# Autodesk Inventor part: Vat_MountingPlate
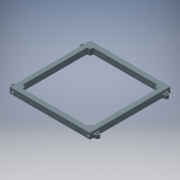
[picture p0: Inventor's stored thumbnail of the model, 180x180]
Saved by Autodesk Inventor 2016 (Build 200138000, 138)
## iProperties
Created: 2015-11
Part Number: Vat_MountingPlate
Material: Generic
Document SubType Name: Modeling
Designer: John
Density: 1 g/cm^3
Appearance: Default
Author: John
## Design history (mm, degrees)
feature "Base1"
sketch "Sketch1"
  geometry: L1 (8, 17.2)-(8, 16.2) reference; L2 (3.5, 20.7)-(4.5, 20.7) reference; L3 (0, 0)-(0, 24.2) reference; L4 (187.3, 0)-(0, 0) reference; L5 (187.3, 0)-(187.3, 24.2) reference; L6 (183.8, 20.7)-(182.8, 20.7) reference; L7 (179.3, 17.2)-(179.3, 16.2) reference; L8 (175.8, 12.7)-(11.5, 12.7) reference; L9 (3.5, 192)-(4.5, 192) reference; L10 (8, 195.5)-(8, 196.5) reference; L11 (11.5, 200)-(175.8, 200) reference; L12 (179.3, 195.5)-(179.3, 196.5) reference; L13 (183.8, 192)-(182.8, 192) reference; L14 (187.3, 188.5)-(187.3, 212.7) reference; L15 (187.3, 212.7)-(0, 212.7) reference; L16 (0, 188.5)-(0, 212.7) reference; C1 r 1.75 at (183.3, 16.7) reference; C2 r 1.75 at (4, 16.7) reference; C3 r 1.75 at (4, 196) reference; C4 r 1.75 at (183.3, 196) reference; A1 r 3.5 centre (4.5, 17.2) between (8, 17.2) and (4.5, 20.7) reference; A2 r 3.5 centre (3.5, 24.2) between (0, 24.2) and (3.5, 20.7) reference; A3 r 3.5 centre (183.8, 24.2) between (183.8, 20.7) and (187.3, 24.2) reference; A4 r 3.5 centre (182.8, 17.2) between (182.8, 20.7) and (179.3, 17.2) reference; A5 r 3.5 centre (175.8, 16.2) between (175.8, 12.7) and (179.3, 16.2) reference; A6 r 3.5 centre (11.5, 16.2) between (8, 16.2) and (11.5, 12.7) reference; A7 r 3.5 centre (4.5, 195.5) between (4.5, 192) and (8, 195.5) reference; A8 r 3.5 centre (11.5, 196.5) between (11.5, 200) and (8, 196.5) reference; A9 r 3.5 centre (175.8, 196.5) between (179.3, 196.5) and (175.8, 200) reference; A10 r 3.5 centre (182.8, 195.5) between (179.3, 195.5) and (182.8, 192) reference; A11 r 3.5 centre (183.8, 188.5) between (187.3, 188.5) and (183.8, 192) reference; A12 r 3.5 centre (3.5, 188.5) between (3.5, 192) and (0, 188.5) reference; 1 further point
extrude "Extrusion1" join sketch "Sketch1" stored distance "d0" = 10; taper "d1" = 0 deg
sketch "Sketch2"
  geometry: L1 (212.7, 19.35)-(212.7, 0) reference; L2 (210.7, 21.35)-(202, 21.35) reference; L3 (200, 19.35)-(200, 21.35) reference; L4 (12.7, 21.35)-(200, 21.35) reference; L5 (12.7, 19.35)-(12.7, 21.35) reference; L6 (2, 21.35)-(10.7, 21.35) reference; L7 (0, 0)-(0, 19.35) reference; L8 (212.7, 0)-(0, 0) reference; L9 (202, 21.35)-(200, 21.35); L10 (10.7, 21.35)-(12.7, 21.35); C1 r 4.25 at (6.35, 13.85) reference; C2 r 4.25 at (206.35, 13.85) reference; A1 r 2 centre (210.7, 19.35) between (212.7, 19.35) and (210.7, 21.35) reference; A2 r 2 centre (202, 19.35) between (202, 21.35) and (200, 19.35) reference; A3 r 2 centre (10.7, 19.35) between (12.7, 19.35) and (10.7, 21.35) reference; A4 r 2 centre (2, 19.35) between (2, 21.35) and (0, 19.35) reference; 1 further point
  constraints: 4 end point, 1 collinear, 1 horizontal, 1 tangent
extrude "Extrusion2" join sketch "Sketch2" stored distance "d2" = 10; taper "d3" = 0 deg
sketch "Sketch3"
  geometry: L1 (212.7, -25)-(212.7, -187.7) reference; L2 (212.7, 0)-(212.7, -5) reference; L3 (0, 0)-(212.7, 0) reference; L4 (0, 0)-(0, -5) reference; L5 (0, -25)-(0, -187.7) reference; L6 (0, -207.7)-(0, -212.7) reference; L7 (0, -212.7)-(212.7, -212.7) reference; L8 (212.7, -207.7)-(212.7, -212.7) reference; L9 (17.2, -20.7)-(16.2, -20.7) reference; L10 (20.7, -16.2)-(20.7, -17.2) reference; L11 (188.5, -12.7)-(24.2, -12.7) reference; L12 (192, -16.2)-(192, -17.2) reference; L13 (195.5, -20.7)-(196.5, -20.7) reference; L14 (200, -188.5)-(200, -24.2) reference; L15 (195.5, -192)-(196.5, -192) reference; L16 (192, -196.5)-(192, -195.5) reference; L17 (24.2, -200)-(188.5, -200) reference; L18 (20.7, -196.5)-(20.7, -195.5) reference; L19 (17.2, -192)-(16.2, -192) reference; L20 (12.7, -24.2)-(12.7, -188.5) reference; C1 r 1.75 at (196, -16.7) reference; C2 r 1.75 at (16.7, -16.7) reference; C3 r 1.75 at (16.7, -196) reference; C4 r 1.75 at (196, -196) reference; C5 r 1.75 at (217.7, -197.7) reference; C6 r 1.75 at (-5, -197.7) reference; C7 r 1.75 at (-5, -15) reference; C8 r 1.75 at (217.7, -15) reference; A1 r 5 centre (217.7, -25) between (217.7, -20) and (212.7, -25) reference; A2 r 5 centre (217.7, -15) between (217.7, -20) and (217.7, -10) reference; A3 r 5 centre (217.7, -5) between (212.7, -5) and (217.7, -10) reference; A4 r 5 centre (-5, -5) between (-5, -10) and (0, -5) reference; A5 r 5 centre (-5, -15) between (-5, -10) and (-5, -20) reference; A6 r 5 centre (-5, -25) between (0, -25) and (-5, -20) reference; A7 r 5 centre (-5, -187.7) between (-5, -192.7) and (0, -187.7) reference; A8 r 5 centre (-5, -197.7) between (-5, -192.7) and (-5, -202.7) reference; A9 r 5 centre (-5, -207.7) between (0, -207.7) and (-5, -202.7) reference; A10 r 5 centre (217.7, -207.7) between (217.7, -202.7) and (212.7, -207.7) reference; A11 r 5 centre (217.7, -197.7) between (217.7, -202.7) and (217.7, -192.7) reference; A12 r 5 centre (217.7, -187.7) between (212.7, -187.7) and (217.7, -192.7) reference; A13 r 3.5 centre (17.2, -17.2) between (17.2, -20.7) and (20.7, -17.2) reference; A14 r 3.5 centre (24.2, -16.2) between (24.2, -12.7) and (20.7, -16.2) reference; A15 r 3.5 centre (188.5, -16.2) between (192, -16.2) and (188.5, -12.7) reference; A16 r 3.5 centre (195.5, -17.2) between (192, -17.2) and (195.5, -20.7) reference; A17 r 3.5 centre (196.5, -24.2) between (200, -24.2) and (196.5, -20.7) reference; A18 r 3.5 centre (196.5, -188.5) between (196.5, -192) and (200, -188.5) reference; A19 r 3.5 centre (195.5, -195.5) between (195.5, -192) and (192, -195.5) reference; A20 r 3.5 centre (188.5, -196.5) between (188.5, -200) and (192, -196.5) reference; A21 r 3.5 centre (24.2, -196.5) between (20.7, -196.5) and (24.2, -200) reference; A22 r 3.5 centre (17.2, -195.5) between (20.7, -195.5) and (17.2, -192) reference; A23 r 3.5 centre (16.2, -188.5) between (12.7, -188.5) and (16.2, -192) reference; A24 r 3.5 centre (16.2, -24.2) between (16.2, -20.7) and (12.7, -24.2) reference; 1 further point
extrude "Extrusion3" cut sketch "Sketch3" distance "d4" = 6; taper "d5" = 0 deg
sketch "Sketch4"
  geometry: L1 (17.2, -20.7)-(16.2, -20.7) reference; L2 (20.7, -16.2)-(20.7, -17.2) reference; L3 (188.5, -12.7)-(24.2, -12.7) reference; L4 (192, -17.2)-(192, -16.2) reference; L5 (196.5, -20.7)-(195.5, -20.7) reference; L6 (200, -188.5)-(200, -24.2) reference; L7 (195.5, -192)-(196.5, -192) reference; L8 (192, -196.5)-(192, -195.5) reference; L9 (24.2, -200)-(188.5, -200) reference; L10 (20.7, -195.5)-(20.7, -196.5) reference; L11 (16.2, -192)-(17.2, -192) reference; L12 (12.7, -24.2)-(12.7, -188.5) reference; L13 (212.7, -25)-(212.7, -187.7) reference; L14 (212.7, 0)-(212.7, -5) reference; L15 (0, 0)-(212.7, 0) reference; L16 (0, -5)-(0, 0) reference; L17 (0, -187.7)-(0, -25) reference; L18 (0, -212.7)-(0, -207.7) reference; L19 (212.7, -212.7)-(0, -212.7) reference; L20 (212.7, -207.7)-(212.7, -212.7) reference; C1 r 1.75 at (217.7, -15) reference; C2 r 1.75 at (-5, -15) reference; C3 r 1.75 at (-5, -197.7) reference; C4 r 1.75 at (217.7, -197.7) reference; C5 r 1.75 at (196, -196) reference; C6 r 1.75 at (16.7, -196) reference; C7 r 1.75 at (16.7, -16.7) reference; C8 r 1.75 at (196, -16.7) reference; A1 r 3.5 centre (16.2, -24.2) between (16.2, -20.7) and (12.7, -24.2) reference; A2 r 3.5 centre (17.2, -17.2) between (17.2, -20.7) and (20.7, -17.2) reference; A3 r 3.5 centre (24.2, -16.2) between (24.2, -12.7) and (20.7, -16.2) reference; A4 r 3.5 centre (188.5, -16.2) between (192, -16.2) and (188.5, -12.7) reference; A5 r 3.5 centre (195.5, -17.2) between (192, -17.2) and (195.5, -20.7) reference; A6 r 3.5 centre (196.5, -24.2) between (200, -24.2) and (196.5, -20.7) reference; A7 r 3.5 centre (196.5, -188.5) between (196.5, -192) and (200, -188.5) reference; A8 r 3.5 centre (195.5, -195.5) between (195.5, -192) and (192, -195.5) reference; A9 r 3.5 centre (188.5, -196.5) between (188.5, -200) and (192, -196.5) reference; A10 r 3.5 centre (24.2, -196.5) between (20.7, -196.5) and (24.2, -200) reference; A11 r 3.5 centre (17.2, -195.5) between (20.7, -195.5) and (17.2, -192) reference; A12 r 3.5 centre (16.2, -188.5) between (12.7, -188.5) and (16.2, -192) reference; A13 r 5 centre (217.7, -25) between (217.7, -20) and (212.7, -25) reference; A14 r 5 centre (217.7, -15) between (217.7, -20) and (217.7, -10) reference; A15 r 5 centre (217.7, -5) between (212.7, -5) and (217.7, -10) reference; A16 r 5 centre (-5, -5) between (-5, -10) and (0, -5) reference; A17 r 5 centre (-5, -15) between (-5, -10) and (-5, -20) reference; A18 r 5 centre (-5, -25) between (0, -25) and (-5, -20) reference; A19 r 5 centre (-5, -187.7) between (-5, -192.7) and (0, -187.7) reference; A20 r 5 centre (-5, -197.7) between (-5, -192.7) and (-5, -202.7) reference; A21 r 5 centre (-5, -207.7) between (0, -207.7) and (-5, -202.7) reference; A22 r 5 centre (217.7, -207.7) between (217.7, -202.7) and (212.7, -207.7) reference; A23 r 5 centre (217.7, -197.7) between (217.7, -202.7) and (217.7, -192.7) reference; A24 r 5 centre (217.7, -187.7) between (212.7, -187.7) and (217.7, -192.7) reference; 1 further point
extrude "Extrusion4" join sketch "Sketch4" stored distance "d6" = 6; taper "d7" = 0 deg
sketch "Sketch5"
  geometry: L1 (0, 20)-(0, 0) reference; L2 (0, 202.7)-(0, 182.7) reference; L3 (-212.7, 0)-(-212.7, 20) reference; L4 (-212.7, 182.7)-(-212.7, 202.7) reference; L5 (-217.7, 196.049)-(-214.8, 194.374); L6 (-214.8, 194.374)-(-214.8, 191.026); L7 (-214.8, 191.026)-(-217.7, 189.351); L8 (-217.7, 189.351)-(-220.6, 191.026); L9 (-220.6, 191.026)-(-220.6, 194.374); L10 (-220.6, 194.374)-(-217.7, 196.049); L11 (-217.7, 13.349)-(-214.8, 11.674); L12 (-214.8, 11.674)-(-214.8, 8.326); L13 (-214.8, 8.326)-(-217.7, 6.651); L14 (-217.7, 6.651)-(-220.6, 8.326); L15 (-220.6, 8.326)-(-220.6, 11.674); L16 (-220.6, 11.674)-(-217.7, 13.349); L17 (5, 13.349)-(7.9, 11.674); L18 (7.9, 11.674)-(7.9, 8.326); L19 (7.9, 8.326)-(5, 6.651); L20 (5, 6.651)-(2.1, 8.326); L21 (2.1, 8.326)-(2.1, 11.674); L22 (2.1, 11.674)-(5, 13.349); L23 (5, 196.049)-(7.9, 194.374); L24 (7.9, 194.374)-(7.9, 191.026); L25 (7.9, 191.026)-(5, 189.351); L26 (5, 189.351)-(2.1, 191.026); L27 (2.1, 191.026)-(2.1, 194.374); L28 (2.1, 194.374)-(5, 196.049); C1 r 1.75 at (5, 10) reference; C2 r 1.75 at (5, 192.7) reference; C3 r 1.75 at (-217.7, 10) reference; C4 r 1.75 at (-217.7, 192.7) reference; A1 r 5 centre (5, 10) between (5, 5) and (5, 15) reference; A2 r 5 centre (5, 20) between (0, 20) and (5, 15) reference; A3 r 5 centre (5, 0) between (5, 5) and (0, 0) reference; A4 r 5 centre (5, 192.7) between (5, 187.7) and (5, 197.7) reference; A5 r 5 centre (5, 202.7) between (0, 202.7) and (5, 197.7) reference; A6 r 5 centre (5, 182.7) between (5, 187.7) and (0, 182.7) reference; A7 r 5 centre (-217.7, 20) between (-217.7, 15) and (-212.7, 20) reference; A8 r 5 centre (-217.7, 10) between (-217.7, 15) and (-217.7, 5) reference; A9 r 5 centre (-217.7, 0) between (-212.7, 0) and (-217.7, 5) reference; A10 r 5 centre (-217.7, 202.7) between (-217.7, 197.7) and (-212.7, 202.7) reference; A11 r 5 centre (-217.7, 192.7) between (-217.7, 197.7) and (-217.7, 187.7) reference; A12 r 5 centre (-217.7, 182.7) between (-212.7, 182.7) and (-217.7, 187.7) reference; 5 further points
  constraints: 48 end point, 4 coincident, 4 vertical, 3 equal length, 52 other
  dimensions: "d8" = 5.8 distance between parallel lines of L15 L12
extrude "Extrusion5" cut sketch "Sketch5" distance "d9" = 3; taper "d10" = 0 deg
body "Solid1"
node "Projected Loop1"
node "Projected Loop2"
node "Projected Loop3"
node "Projected Loop4"
node "Projected Loop5"
node "Projected Loop6"
node "Projected Loop7"
node "Projected Loop8"
node "Projected Loop9"
